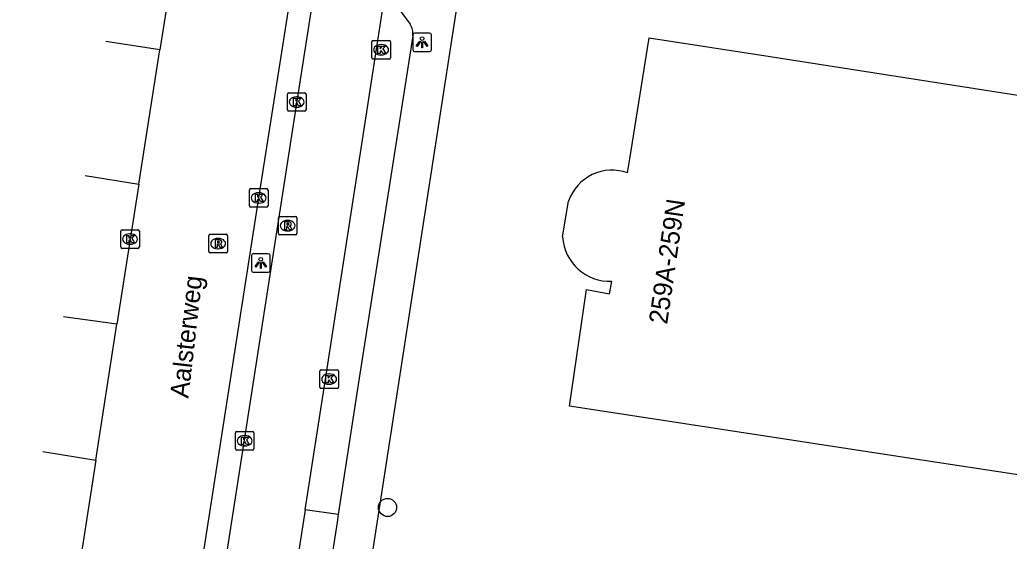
# Model space of a CAD drawing. Extents: x 161486 to 162249, y 379484 to 380829.
# Drawn here: x 161664.7 to 161717.9, y 380629.8 to 380657.8 of the extents above; entities that cross this region are included whole.
import ezdxf

# ---------------------------------------------------------------- set-up
doc = ezdxf.new("R2010")
doc.units = 0
for name, color, linetype in [('IMGEO_Boom', 7, 'Continuous'), ('IMGEO_Kolk', 7, 'Continuous'), ('IMGEO_Lichtpunt', 7, 'Continuous'), ('IMGEO_Openbare_ruimte_label', 7, 'Continuous'), ('IMGEO_Pand', 7, 'Continuous'), ('IMGEO_Pand_nummerreeks', 7, 'Continuous'), ('IMGEO_Parkeervlak_open', 7, 'Continuous'), ('IMGEO_Rijbaan_lokaal_open', 7, 'Continuous'), ('IMGEO_Rijbaan_regionaal_gesloten', 7, 'Continuous'), ('IMGEO_Rioolput', 7, 'Continuous'), ('IMGEO_Voetpad_open', 7, 'Continuous')]:
    doc.layers.add(name, color=color, linetype=linetype)

msp = doc.modelspace()

# ---------------------------------------------------------------- linework, layer by layer
at = {"layer": 'IMGEO_Boom'}
msp.add_circle((161684.469, 380631.602), 0.489, dxfattribs=at)
at = {"layer": 'IMGEO_Kolk'}
for p, q in [((161683.623, 380655.807), (161683.623, 380656.659)), ((161683.698, 380656.733), (161684.55, 380656.733)), ((161684.111, 380656.513), (161684.136, 380656.513)), ((161684.624, 380656.659), (161684.624, 380655.807)), ((161684.134, 380655.953), (161684.109, 380655.953)), ((161684.55, 380655.733), (161683.698, 380655.733)), ((161679.082, 380652.994), (161679.082, 380653.846)), ((161679.157, 380653.92), (161680.009, 380653.92)), ((161680.083, 380653.846), (161680.083, 380652.994)), ((161679.57, 380653.7), (161679.595, 380653.7)), ((161680.009, 380652.92), (161679.157, 380652.92)), ((161679.593, 380653.14), (161679.568, 380653.14)), ((161677.034, 380647.833), (161677.034, 380648.685)), ((161677.109, 380648.759), (161677.961, 380648.759)), ((161677.522, 380648.539), (161677.547, 380648.539)), ((161678.035, 380648.685), (161678.035, 380647.833)), ((161677.545, 380647.979), (161677.52, 380647.979)), ((161677.961, 380647.759), (161677.109, 380647.759)), ((161670.109, 380645.619), (161670.109, 380646.471)), ((161670.184, 380646.545), (161671.036, 380646.545)), ((161670.597, 380646.325), (161670.622, 380646.325)), ((161671.11, 380646.471), (161671.11, 380645.619)), ((161670.62, 380645.765), (161670.595, 380645.765)), ((161671.036, 380645.545), (161670.184, 380645.545)), ((161680.825, 380638.082), (161680.825, 380638.934)), ((161680.9, 380639.008), (161681.752, 380639.008)), ((161681.826, 380638.934), (161681.826, 380638.082)), ((161681.313, 380638.788), (161681.338, 380638.788)), ((161681.752, 380638.008), (161680.9, 380638.008)), ((161681.336, 380638.228), (161681.311, 380638.228)), ((161676.354, 380635.689), (161677.206, 380635.689)), ((161676.279, 380634.763), (161676.279, 380635.615)), ((161676.767, 380635.469), (161676.792, 380635.469)), ((161677.28, 380635.615), (161677.28, 380634.763)), ((161677.206, 380634.689), (161676.354, 380634.689)), ((161676.79, 380634.909), (161676.765, 380634.909))]:
    msp.add_line(p, q, dxfattribs=at)
for points in [[(161683.623, 380655.807), (161683.623, 380656.659)], [(161683.698, 380656.733), (161684.55, 380656.733)], [(161683.944, 380656.433), (161684.067, 380656.433), (161684.067, 380656.282), (161684.197, 380656.433), (161684.361, 380656.433), (161684.215, 380656.282), (161684.368, 380656.033), (161684.216, 380656.033), (161684.131, 380656.197), (161684.067, 380656.13), (161684.067, 380656.033), (161683.944, 380656.033), (161683.944, 380656.433)], [(161684.624, 380656.659), (161684.624, 380655.807)], [(161684.55, 380655.733), (161683.698, 380655.733)], [(161679.082, 380652.994), (161679.082, 380653.846)], [(161679.157, 380653.92), (161680.009, 380653.92)], [(161680.083, 380653.846), (161680.083, 380652.994)], [(161679.403, 380653.62), (161679.526, 380653.62), (161679.526, 380653.469), (161679.656, 380653.62), (161679.82, 380653.62), (161679.674, 380653.469), (161679.827, 380653.22), (161679.675, 380653.22), (161679.59, 380653.384), (161679.526, 380653.317), (161679.526, 380653.22), (161679.403, 380653.22), (161679.403, 380653.62)], [(161680.009, 380652.92), (161679.157, 380652.92)], [(161677.034, 380647.833), (161677.034, 380648.685)], [(161677.109, 380648.759), (161677.961, 380648.759)], [(161677.355, 380648.459), (161677.478, 380648.459), (161677.478, 380648.308), (161677.608, 380648.459), (161677.772, 380648.459), (161677.626, 380648.308), (161677.779, 380648.059), (161677.627, 380648.059), (161677.542, 380648.223), (161677.478, 380648.156), (161677.478, 380648.059), (161677.355, 380648.059), (161677.355, 380648.459)], [(161678.035, 380648.685), (161678.035, 380647.833)], [(161677.961, 380647.759), (161677.109, 380647.759)], [(161670.109, 380645.619), (161670.109, 380646.471)], [(161670.184, 380646.545), (161671.036, 380646.545)], [(161671.11, 380646.471), (161671.11, 380645.619)], [(161670.43, 380646.245), (161670.553, 380646.245), (161670.553, 380646.094), (161670.683, 380646.245), (161670.847, 380646.245), (161670.701, 380646.094), (161670.854, 380645.845), (161670.702, 380645.845), (161670.617, 380646.009), (161670.553, 380645.942), (161670.553, 380645.845), (161670.43, 380645.845), (161670.43, 380646.245)], [(161671.036, 380645.545), (161670.184, 380645.545)], [(161680.825, 380638.082), (161680.825, 380638.934)], [(161680.9, 380639.008), (161681.752, 380639.008)], [(161681.826, 380638.934), (161681.826, 380638.082)], [(161681.146, 380638.708), (161681.269, 380638.708), (161681.269, 380638.557), (161681.399, 380638.708), (161681.563, 380638.708), (161681.417, 380638.557), (161681.57, 380638.308), (161681.418, 380638.308), (161681.333, 380638.472), (161681.269, 380638.405), (161681.269, 380638.308), (161681.146, 380638.308), (161681.146, 380638.708)], [(161681.752, 380638.008), (161680.9, 380638.008)], [(161676.354, 380635.689), (161677.206, 380635.689)], [(161676.279, 380634.763), (161676.279, 380635.615)], [(161676.6, 380635.389), (161676.723, 380635.389), (161676.723, 380635.238), (161676.853, 380635.389), (161677.017, 380635.389), (161676.871, 380635.238), (161677.024, 380634.989), (161676.872, 380634.989), (161676.787, 380635.153), (161676.723, 380635.086), (161676.723, 380634.989), (161676.6, 380634.989), (161676.6, 380635.389)], [(161677.28, 380635.615), (161677.28, 380634.763)], [(161677.206, 380634.689), (161676.354, 380634.689)]]:
    msp.add_lwpolyline(points, dxfattribs=at)
for centre, start, end in [((161683.7, 380656.657), 91.552, 178.448), ((161683.7, 380656.657), 91.552, 178.448), ((161684.548, 380656.657), 1.552, 88.448), ((161684.548, 380656.657), 1.552, 88.448), ((161683.7, 380655.809), 181.552, 268.448), ((161683.7, 380655.809), 181.552, 268.448), ((161684.548, 380655.809), 271.552, 358.448), ((161684.548, 380655.809), 271.552, 358.448), ((161679.159, 380653.844), 91.552, 178.448), ((161679.159, 380653.844), 91.552, 178.448), ((161680.007, 380653.844), 1.552, 88.448), ((161680.007, 380653.844), 1.552, 88.448), ((161679.159, 380652.996), 181.552, 268.448), ((161679.159, 380652.996), 181.552, 268.448), ((161680.007, 380652.996), 271.552, 358.448), ((161680.007, 380652.996), 271.552, 358.448), ((161677.111, 380648.683), 91.552, 178.448), ((161677.111, 380648.683), 91.552, 178.448), ((161677.959, 380648.683), 1.552, 88.448), ((161677.959, 380648.683), 1.552, 88.448), ((161677.111, 380647.835), 181.552, 268.448), ((161677.111, 380647.835), 181.552, 268.448), ((161677.959, 380647.835), 271.552, 358.448), ((161677.959, 380647.835), 271.552, 358.448), ((161670.186, 380646.469), 91.552, 178.448), ((161670.186, 380646.469), 91.552, 178.448), ((161671.034, 380646.469), 1.552, 88.448), ((161671.034, 380646.469), 1.552, 88.448), ((161670.186, 380645.621), 181.552, 268.448), ((161670.186, 380645.621), 181.552, 268.448), ((161671.034, 380645.621), 271.552, 358.448), ((161671.034, 380645.621), 271.552, 358.448), ((161680.902, 380638.932), 91.552, 178.448), ((161680.902, 380638.932), 91.552, 178.448), ((161681.75, 380638.932), 1.552, 88.448), ((161681.75, 380638.932), 1.552, 88.448), ((161680.902, 380638.084), 181.552, 268.448), ((161680.902, 380638.084), 181.552, 268.448), ((161681.75, 380638.084), 271.552, 358.448), ((161681.75, 380638.084), 271.552, 358.448), ((161676.356, 380635.613), 91.552, 178.448), ((161676.356, 380635.613), 91.552, 178.448), ((161677.204, 380635.613), 1.552, 88.448), ((161677.204, 380635.613), 1.552, 88.448), ((161676.356, 380634.765), 181.552, 268.448), ((161676.356, 380634.765), 181.552, 268.448), ((161677.204, 380634.765), 271.552, 358.448), ((161677.204, 380634.765), 271.552, 358.448)]:
    msp.add_arc(centre, 0.0765, start, end, dxfattribs=at)
for centre, major_axis, ratio, start_param, end_param in [((161684.11, 380656.233), (-0.387, 0.002), 0.722429, 4.712389, 7.853982), ((161684.135, 380656.233), (-0.39, 0.002), 0.717154, 1.570796, 4.712389), ((161679.569, 380653.42), (-0.387, 0.002), 0.722429, 4.712389, 7.853982), ((161679.594, 380653.42), (-0.39, 0.002), 0.717154, 1.570796, 4.712389), ((161677.521, 380648.259), (-0.387, 0.002), 0.722429, 4.712389, 7.853982), ((161677.546, 380648.259), (-0.39, 0.002), 0.717154, 1.570796, 4.712389), ((161670.596, 380646.045), (-0.387, 0.002), 0.722429, 4.712389, 7.853982), ((161670.621, 380646.045), (-0.39, 0.002), 0.717154, 1.570796, 4.712389), ((161681.312, 380638.508), (-0.387, 0.002), 0.722429, 4.712389, 7.853982), ((161681.337, 380638.508), (-0.39, 0.002), 0.717154, 1.570796, 4.712389), ((161676.766, 380635.189), (-0.387, 0.002), 0.722429, 4.712389, 7.853982), ((161676.791, 380635.189), (-0.39, 0.002), 0.717154, 1.570796, 4.712389)]:
    msp.add_ellipse(centre, major_axis=major_axis, ratio=ratio, start_param=start_param, end_param=end_param, dxfattribs=at)
at = {"layer": 'IMGEO_Lichtpunt'}
for p, q in [((161685.831, 380657.035), (161685.831, 380656.228)), ((161685.831, 380657.035), (161685.831, 380656.228)), ((161686.733, 380657.13), (161685.925, 380657.13)), ((161686.733, 380657.13), (161685.925, 380657.13)), ((161686.827, 380656.228), (161686.827, 380657.035)), ((161686.827, 380656.228), (161686.827, 380657.035)), ((161685.925, 380656.134), (161686.733, 380656.134)), ((161685.925, 380656.134), (161686.733, 380656.134)), ((161678.05, 380645.257), (161677.242, 380645.257)), ((161678.05, 380645.257), (161677.242, 380645.257)), ((161677.148, 380645.162), (161677.148, 380644.355)), ((161677.148, 380645.162), (161677.148, 380644.355)), ((161678.144, 380644.355), (161678.144, 380645.162)), ((161678.144, 380644.355), (161678.144, 380645.162)), ((161677.242, 380644.261), (161678.05, 380644.261)), ((161677.242, 380644.261), (161678.05, 380644.261))]:
    msp.add_line(p, q, dxfattribs=at)
for points in [[(161686.205, 380656.699), (161686.244, 380656.671), (161686.056, 380656.409), (161686.018, 380656.436), (161686.205, 380656.699)], [(161686.307, 380656.651), (161686.354, 380656.651), (161686.354, 380656.329), (161686.307, 380656.329), (161686.307, 380656.651)], [(161686.417, 380656.671), (161686.455, 380656.698), (161686.642, 380656.436), (161686.603, 380656.408), (161686.417, 380656.671)], [(161677.522, 380644.826), (161677.561, 380644.798), (161677.373, 380644.536), (161677.335, 380644.563), (161677.522, 380644.826)], [(161677.624, 380644.778), (161677.671, 380644.778), (161677.671, 380644.456), (161677.624, 380644.456), (161677.624, 380644.778)], [(161677.734, 380644.798), (161677.772, 380644.825), (161677.959, 380644.563), (161677.92, 380644.535), (161677.734, 380644.798)]]:
    msp.add_lwpolyline(points, dxfattribs=at)
for centre in [(161686.33, 380656.833), (161677.647, 380644.96)]:
    msp.add_circle(centre, 0.0994, dxfattribs=at)
for centre, start, end in [((161685.925, 380657.035), 90, 180), ((161685.925, 380657.035), 90, 180), ((161686.733, 380657.035), 0, 90), ((161686.733, 380657.035), 0, 90), ((161685.925, 380656.228), 180, 270), ((161685.925, 380656.228), 180, 270), ((161686.733, 380656.228), 270, 0), ((161686.733, 380656.228), 270, 360), ((161677.242, 380645.162), 90, 180), ((161677.242, 380645.162), 90, 180), ((161678.05, 380645.162), 0, 90), ((161678.05, 380645.162), 0, 90), ((161677.242, 380644.355), 180, 270), ((161677.242, 380644.355), 180, 270), ((161678.05, 380644.355), 270, 0), ((161678.05, 380644.355), 270, 360)]:
    msp.add_arc(centre, 0.0946, start, end, dxfattribs=at)
at = {"layer": 'IMGEO_Pand'}
for points in [[(161697.39, 380649.604), (161697.512, 380650.372), (161698.549, 380656.877), (161705.065, 380655.863), (161722.876, 380653.093), (161720.793, 380639.456)], [(161693.886, 380646.173), (161694.213, 380648.086)], [(161720.793, 380639.456), (161719.827, 380633.134), (161713.224, 380634.145), (161694.271, 380637.046), (161695.181, 380643.332), (161696.411, 380643.093), (161696.543, 380643.772)]]:
    msp.add_lwpolyline(points, dxfattribs=at)
for centre, radius, start, end in [((161696.546, 380647.287), 2.466, 69.9893, 161.0885), ((161696.452, 380646.342), 2.572, 183.7719, 272.023)]:
    msp.add_arc(centre, radius, start, end, dxfattribs=at)
at = {"layer": 'IMGEO_Parkeervlak_open'}
msp.add_lwpolyline([(161681.815, 380631.23), (161680.036, 380631.48)], dxfattribs=at)
at = {"layer": 'IMGEO_Rijbaan_lokaal_open'}
for points in [[(161670.173, 380593.181), (161670.306, 380593.817), (161673.164, 380612.049), (161679.792, 380654.611), (161681.911, 380668.265), (161681.466, 380668.839)], [(161680.036, 380631.48), (161681.18, 380638.847), (161684.483, 380660.221)], [(161672.217, 380656.223), (161669.298, 380656.679)], [(161668.194, 380649.472), (161671.075, 380648.991)], [(161669.899, 380641.459), (161667.027, 380641.859)], [(161665.917, 380634.621), (161668.766, 380634.148)], [(161680.036, 380631.48), (161679.125, 380625.608)]]:
    msp.add_lwpolyline(points, dxfattribs=at)
at = {"layer": 'IMGEO_Rijbaan_regionaal_gesloten'}
for points in [[(161665.377, 380568.264), (161666.644, 380577.811), (161667.768, 380585.303), (161668.85, 380592.276), (161670.749, 380604.536), (161673.878, 380624.77), (161677.535, 380648.259), (161680.22, 380665.224), (161680.68, 380668.409), (161683.394, 380685.989), (161683.565, 380687.03), (161683.651, 380687.555), (161684.438, 380692.656), (161687.73, 380713.853), (161689.372, 380724.138), (161690.713, 380733.056), (161692.699, 380746.151), (161693.32, 380750.34), (161693.892, 380754.498), (161694.597, 380759.447), (161695.308, 380764.889), (161696.352, 380772.576), (161696.737, 380775.208), (161698.248, 380785.538)], [(161674.184, 380668.798), (161673.65, 380665.298), (161672.217, 380656.223)], [(161668.85, 380592.276), (161670.749, 380604.536), (161673.878, 380624.77), (161677.535, 380648.259), (161680.22, 380665.224), (161680.68, 380668.409)], [(161671.075, 380648.991), (161672.217, 380656.223)], [(161671.075, 380648.991), (161670.61, 380646.045), (161669.899, 380641.459)], [(161668.766, 380634.148), (161669.899, 380641.459)], [(161668.766, 380634.148), (161667.475, 380625.818), (161664.782, 380608.542), (161664.675, 380607.854)]]:
    msp.add_lwpolyline(points, dxfattribs=at)
at = {"layer": 'IMGEO_Rioolput'}
for p, q in [((161678.592, 380646.34), (161678.592, 380647.192)), ((161678.667, 380647.266), (161679.519, 380647.266)), ((161679.08, 380647.046), (161679.105, 380647.046)), ((161679.593, 380647.192), (161679.593, 380646.34)), ((161674.925, 380646.302), (161675.777, 380646.302)), ((161679.103, 380646.486), (161679.078, 380646.486)), ((161674.85, 380645.376), (161674.85, 380646.228)), ((161675.338, 380646.082), (161675.363, 380646.082)), ((161675.851, 380646.228), (161675.851, 380645.376)), ((161679.519, 380646.266), (161678.667, 380646.266)), ((161675.777, 380645.302), (161674.925, 380645.302)), ((161675.361, 380645.522), (161675.336, 380645.522))]:
    msp.add_line(p, q, dxfattribs=at)
for points in [[(161678.592, 380646.34), (161678.592, 380647.192)], [(161678.667, 380647.266), (161679.519, 380647.266)], [(161679.181, 380646.964), (161678.929, 380646.966), (161678.929, 380646.566)], [(161679.107, 380646.885), (161679.053, 380646.885), (161679.053, 380646.804)], [(161679.593, 380647.192), (161679.593, 380646.34)], [(161674.925, 380646.302), (161675.777, 380646.302)], [(161678.929, 380646.566), (161679.053, 380646.566), (161679.053, 380646.728), (161679.064, 380646.728)], [(161679.053, 380646.804), (161679.105, 380646.804)], [(161679.111, 380646.699), (161679.182, 380646.566), (161679.322, 380646.566), (161679.257, 380646.692)], [(161674.85, 380645.376), (161674.85, 380646.228)], [(161675.439, 380646), (161675.187, 380646.002), (161675.187, 380645.602)], [(161675.187, 380645.602), (161675.311, 380645.602), (161675.311, 380645.764), (161675.322, 380645.764)], [(161675.365, 380645.921), (161675.311, 380645.921), (161675.311, 380645.84)], [(161675.311, 380645.84), (161675.363, 380645.84)], [(161675.851, 380646.228), (161675.851, 380645.376)], [(161679.519, 380646.266), (161678.667, 380646.266)], [(161675.777, 380645.302), (161674.925, 380645.302)], [(161675.369, 380645.735), (161675.44, 380645.602), (161675.58, 380645.602), (161675.515, 380645.728)]]:
    msp.add_lwpolyline(points, dxfattribs=at)
for centre, radius, start, end in [((161678.669, 380647.19), 0.0765, 91.552, 178.448), ((161678.669, 380647.19), 0.0765, 91.552, 178.448), ((161679.113, 380646.789), 0.0964, 77.0061, 93.1865), ((161679.127, 380646.846), 0.0378, 276.6634, 79.6772), ((161679.18, 380646.854), 0.109, 350.3612, 89.416), ((161679.178, 380646.854), 0.112, 277.5842, 350.9817), ((161679.517, 380647.19), 0.0765, 1.552, 88.448), ((161679.517, 380647.19), 0.0765, 1.552, 88.448), ((161674.927, 380646.226), 0.0765, 91.552, 178.448), ((161674.927, 380646.226), 0.0765, 91.552, 178.448), ((161675.775, 380646.226), 0.0765, 1.552, 88.448), ((161675.775, 380646.226), 0.0765, 1.552, 88.448), ((161678.669, 380646.342), 0.0765, 181.552, 268.448), ((161678.669, 380646.342), 0.0765, 181.552, 268.448), ((161679.063, 380646.675), 0.0533, 26.0293, 88.6989), ((161679.089, 380646.993), 0.19, 274.7715, 282.9687), ((161679.162, 380646.639), 0.108, 29.5134, 73.7905), ((161679.517, 380646.342), 0.0765, 271.552, 358.448), ((161679.517, 380646.342), 0.0765, 271.552, 358.448), ((161675.321, 380645.711), 0.0533, 26.0293, 88.6989), ((161675.347, 380646.029), 0.19, 274.7715, 282.9687), ((161675.371, 380645.825), 0.0964, 77.0061, 93.1865), ((161675.385, 380645.882), 0.0378, 276.6634, 79.6772), ((161675.438, 380645.89), 0.109, 350.3612, 89.416), ((161675.436, 380645.89), 0.112, 277.5842, 350.9817), ((161675.42, 380645.675), 0.108, 29.5134, 73.7905), ((161674.927, 380645.378), 0.0765, 181.552, 268.448), ((161674.927, 380645.378), 0.0765, 181.552, 268.448), ((161675.775, 380645.378), 0.0765, 271.552, 358.448), ((161675.775, 380645.378), 0.0765, 271.552, 358.448)]:
    msp.add_arc(centre, radius, start, end, dxfattribs=at)
for centre, major_axis, ratio, start_param, end_param in [((161679.079, 380646.766), (-0.387, 0.002), 0.722429, 4.712389, 7.853982), ((161679.104, 380646.766), (-0.39, 0.002), 0.717154, 1.570796, 4.712389), ((161675.337, 380645.802), (-0.387, 0.002), 0.722429, 4.712389, 7.853982), ((161675.362, 380645.802), (-0.39, 0.002), 0.717154, 1.570796, 4.712389)]:
    msp.add_ellipse(centre, major_axis=major_axis, ratio=ratio, start_param=start_param, end_param=end_param, dxfattribs=at)
at = {"layer": 'IMGEO_Voetpad_open'}
for points in [[(161689.026, 380663.962), (161684.141, 380632.376), (161683.425, 380627.743), (161680.38, 380605.802), (161680.26, 380605.833), (161679.923, 380603.696), (161679.803, 380603.707), (161679.209, 380599.887)], [(161684.813, 380658.793), (161685.687, 380657.612)], [(161685.826, 380656.976), (161682.892, 380638.222), (161681.815, 380631.23)], [(161681.815, 380631.23), (161681.749, 380630.803), (161680.917, 380625.4)]]:
    msp.add_lwpolyline(points, dxfattribs=at)
msp.add_arc((161684.858, 380657.098), 0.975, 352.8353, 31.8213, dxfattribs=at)

# ---------------------------------------------------------------- texts
at = {"layer": 'IMGEO_Openbare_ruimte_label'}
msp.add_text('Aalsterweg', height=1, rotation=83.394, dxfattribs=at).set_placement((161673.747, 380637.45))
at = {"layer": 'IMGEO_Pand_nummerreeks'}
msp.add_text('259A-259N', height=1, rotation=81.7365, dxfattribs=at).set_placement((161699.516, 380641.427))

doc.saveas('drawing.dxf')
